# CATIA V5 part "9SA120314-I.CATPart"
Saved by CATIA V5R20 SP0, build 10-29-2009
Part number: 9SA120314-I
Revision: ANY
Definition: UNKNOWN
Nomenclature: 9SA120314-I
Source: Unknown
Bounding box of the stored display mesh (mm): x -3.519 to 3.519, y -12 to 3, z -3.7 to 3.7
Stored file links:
  C:\Users\Utente\Desktop\IO LAVORO\3D X SITO CF\CUMSA\3D files SA\SA 120314\9SA120314-I.CATPart
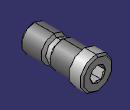
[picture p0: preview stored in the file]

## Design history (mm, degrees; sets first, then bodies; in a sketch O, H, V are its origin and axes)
Body1 "Chaflán3" (main body)
  Solid1: solid without history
